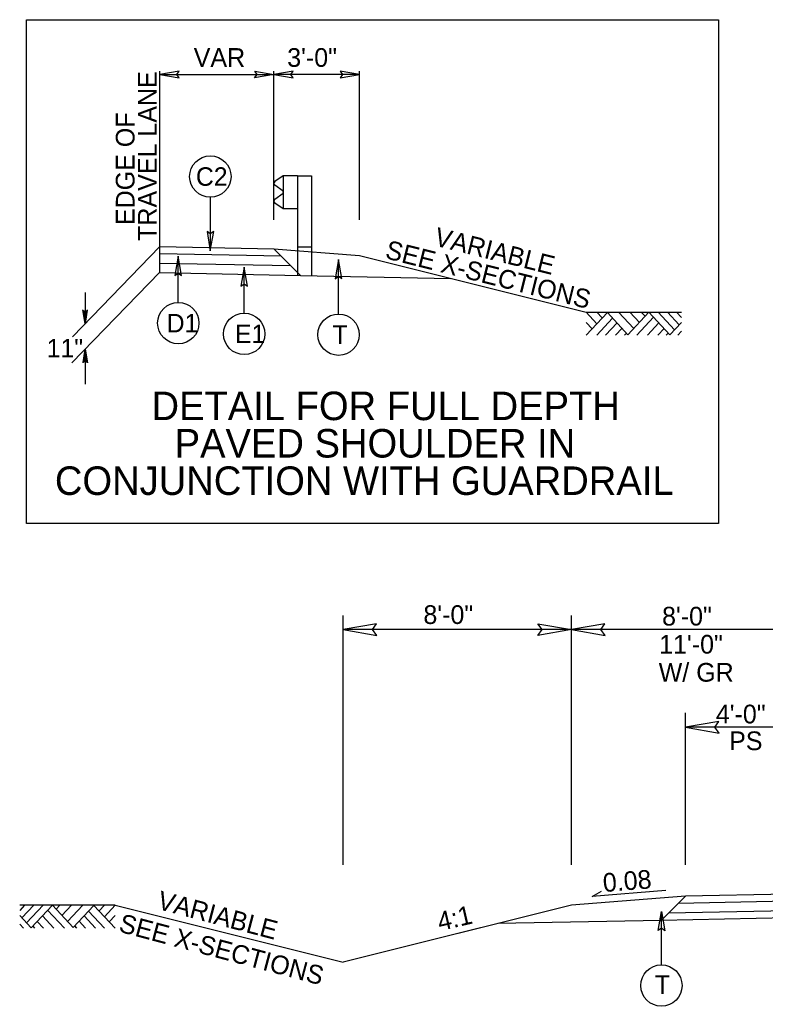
# Model space of a CAD drawing. Extents: x 1901582 to 1902252, y 193723 to 194156.
# Drawn here: x 1902035.74 to 1902061.88, y 194070.53 to 194105.11 of the extents above; entities that cross this region are included whole.
import ezdxf

# ---------------------------------------------------------------- set-up
doc = ezdxf.new("R2010")
doc.units = 0
for name, color, linetype in [('Old_Level_1', 7, 'Continuous'), ('Old_Level_11', 7, 'Continuous'), ('Old_Level_2', 7, 'Continuous'), ('Old_Level_20', 7, 'Continuous'), ('Prop Dimension Text', 7, 'Continuous'), ('Typical Guardrail CELL', 7, 'Continuous'), ('Typical Pavement Slope Information CELL', 7, 'Continuous'), ('Typical Slope Point Local CELL', 7, 'Continuous'), ('Typical Terminator CELL', 7, 'Continuous')]:
    doc.layers.add(name, color=color, linetype=linetype)

msp = doc.modelspace()

# ---------------------------------------------------------------- linework, layer by layer
at = {"layer": 'Old_Level_1'}
for p, q in [((1902040.658, 194096.249), (1902040.658, 194103.306)), ((1902040.658, 194103.19), (1902044.658, 194103.19)), ((1902044.658, 194098.102), (1902044.658, 194103.307)), ((1902044.658, 194098.102), (1902044.658, 194103.306)), ((1902047.658, 194103.19), (1902044.658, 194103.19)), ((1902047.658, 194098.102), (1902047.658, 194103.307)), ((1902040.658, 194097.166), (1902037.59, 194093.996)), ((1902040.655, 194096.916), (1902044.913, 194096.831)), ((1902040.66, 194097.166), (1902044.658, 194097.086)), ((1902044.658, 194097.086), (1902047.658, 194096.846)), ((1902044.658, 194097.086), (1902045.593, 194096.151)), ((1902040.648, 194096.583), (1902045.253, 194096.491)), ((1902047.658, 194096.846), (1902055.605, 194094.859)), ((1902040.641, 194096.25), (1902037.573, 194093.08)), ((1902040.641, 194096.25), (1902045.593, 194096.151)), ((1902045.593, 194096.151), (1902050.861, 194096.045)), ((1902038.039, 194095.548), (1902038.039, 194094.46)), ((1902038.039, 194094.46), (1902037.954, 194094.937)), ((1902038.039, 194094.46), (1902037.966, 194094.928)), ((1902037.978, 194094.919), (1902038.039, 194094.46)), ((1902038.039, 194094.46), (1902037.99, 194094.911)), ((1902038.003, 194094.902), (1902038.039, 194094.46)), ((1902038.039, 194094.46), (1902038.015, 194094.893)), ((1902038.027, 194094.884), (1902038.039, 194094.46)), ((1902038.039, 194094.46), (1902038.123, 194094.937)), ((1902038.111, 194094.928), (1902038.039, 194094.46)), ((1902038.039, 194094.46), (1902038.098, 194094.919)), ((1902038.086, 194094.911), (1902038.039, 194094.46)), ((1902038.039, 194094.46), (1902038.074, 194094.902)), ((1902038.062, 194094.893), (1902038.039, 194094.46)), ((1902038.039, 194094.46), (1902038.05, 194094.884)), ((1902038.039, 194094.875), (1902038.039, 194094.46)), ((1902038.039, 194093.561), (1902037.954, 194093.083)), ((1902037.966, 194093.093), (1902038.039, 194093.561)), ((1902038.039, 194093.561), (1902037.978, 194093.101)), ((1902037.99, 194093.111), (1902038.039, 194093.561)), ((1902038.039, 194093.561), (1902038.003, 194093.119)), ((1902038.015, 194093.127), (1902038.039, 194093.561)), ((1902038.039, 194093.561), (1902038.027, 194093.136)), ((1902038.039, 194093.561), (1902038.123, 194093.083)), ((1902038.05, 194093.136), (1902038.039, 194093.561)), ((1902038.039, 194093.561), (1902038.062, 194093.127)), ((1902038.074, 194093.119), (1902038.039, 194093.561)), ((1902038.039, 194093.561), (1902038.086, 194093.111)), ((1902038.098, 194093.101), (1902038.039, 194093.561)), ((1902038.039, 194093.561), (1902038.111, 194093.093)), ((1902038.039, 194093.561), (1902038.039, 194092.335)), ((1902047.086, 194075.483), (1902047.086, 194084.233)), ((1902055.086, 194075.483), (1902055.086, 194084.233)), ((1902055.086, 194083.733), (1902047.086, 194083.733)), ((1902063.086, 194083.733), (1902055.086, 194083.733)), ((1902059.086, 194075.483), (1902059.086, 194080.814)), ((1902063.086, 194080.314), (1902059.086, 194080.314)), ((1902088.586, 194074.983), (1902059.086, 194074.393)), ((1902088.586, 194074.733), (1902058.831, 194074.138)), ((1902055.086, 194074.073), (1902048.765, 194072.492)), ((1902059.086, 194074.393), (1902055.086, 194074.073)), ((1902058.236, 194073.542), (1902059.086, 194074.393)), ((1902088.586, 194074.149), (1902058.236, 194073.542)), ((1902088.586, 194074.399), (1902058.491, 194073.797)), ((1902058.236, 194073.542), (1902052.506, 194073.428))]:
    msp.add_line(p, q, dxfattribs=at)
for points in [[(1902055.605, 194094.859), (1902058.947, 194094.859)], [(1902039.086, 194074.073), (1902035.744, 194074.073)], [(1902039.086, 194074.073), (1902047.086, 194072.073)], [(1902055.086, 194074.073), (1902047.086, 194072.073)]]:
    msp.add_lwpolyline(points, dxfattribs=at)
at = {"layer": 'Old_Level_11'}
for p, q in [((1902042.427, 194098.89), (1902042.427, 194097.016)), ((1902041.304, 194095.201), (1902041.304, 194096.821)), ((1902046.924, 194094.796), (1902046.924, 194096.708)), ((1902043.614, 194094.825), (1902043.614, 194096.444)), ((1902055.605, 194094.859), (1902055.98, 194094.456)), ((1902055.605, 194094.054), (1902056.347, 194094.851)), ((1902055.98, 194094.859), (1902056.167, 194094.658)), ((1902056.347, 194094.851), (1902057.071, 194094.072)), ((1902056.738, 194094.859), (1902057.271, 194094.286)), ((1902057.071, 194094.072), (1902057.802, 194094.858)), ((1902057.136, 194094.859), (1902057.469, 194094.5)), ((1902057.538, 194094.859), (1902057.671, 194094.716)), ((1902057.802, 194094.858), (1902058.543, 194094.062)), ((1902058.124, 194094.859), (1902058.704, 194094.236)), ((1902058.457, 194094.859), (1902058.871, 194094.415)), ((1902058.777, 194094.859), (1902058.947, 194094.676)), ((1902055.605, 194094.497), (1902055.811, 194094.275)), ((1902055.979, 194094.054), (1902056.533, 194094.65)), ((1902056.288, 194094.054), (1902056.689, 194094.483)), ((1902057.381, 194094.054), (1902057.967, 194094.682)), ((1902057.751, 194094.054), (1902058.151, 194094.483)), ((1902058.543, 194094.062), (1902058.947, 194094.497)), ((1902056.635, 194094.054), (1902056.862, 194094.297)), ((1902056.946, 194094.054), (1902057.017, 194094.13)), ((1902058.117, 194094.054), (1902058.334, 194094.287)), ((1902058.412, 194094.054), (1902058.481, 194094.128)), ((1902058.813, 194094.054), (1902058.947, 194094.197)), ((1902035.914, 194074.073), (1902035.744, 194073.89)), ((1902036.234, 194074.073), (1902035.82, 194073.629)), ((1902036.567, 194074.073), (1902035.987, 194073.45)), ((1902036.889, 194074.072), (1902036.148, 194073.276)), ((1902037.62, 194073.286), (1902036.889, 194074.072)), ((1902037.153, 194074.073), (1902037.02, 194073.93)), ((1902037.555, 194074.073), (1902037.222, 194073.714)), ((1902037.953, 194074.073), (1902037.42, 194073.5)), ((1902038.344, 194074.065), (1902037.62, 194073.286)), ((1902039.086, 194073.268), (1902038.344, 194074.065)), ((1902038.711, 194074.073), (1902038.524, 194073.872)), ((1902039.086, 194074.073), (1902038.711, 194073.67)), ((1902037.31, 194073.268), (1902036.724, 194073.896)), ((1902038.712, 194073.268), (1902038.158, 194073.864)), ((1902058.242, 194071.98), (1902058.242, 194073.855)), ((1902036.148, 194073.276), (1902035.744, 194073.711)), ((1902035.878, 194073.268), (1902035.744, 194073.411)), ((1902036.574, 194073.268), (1902036.357, 194073.501)), ((1902036.94, 194073.268), (1902036.54, 194073.697)), ((1902038.056, 194073.268), (1902037.829, 194073.511)), ((1902038.403, 194073.268), (1902038.002, 194073.697)), ((1902039.086, 194073.711), (1902038.88, 194073.489)), ((1902036.279, 194073.268), (1902036.21, 194073.342)), ((1902037.745, 194073.268), (1902037.674, 194073.344))]:
    msp.add_line(p, q, dxfattribs=at)
for points in [[(1902035.977, 194105.112), (1902060.25, 194105.112), (1902060.25, 194087.454), (1902035.977, 194087.454)], [(1902041.333, 194103.306), (1902040.658, 194103.19), (1902041.337, 194103.07), (1902041.25, 194103.19)], [(1902043.983, 194103.307), (1902044.658, 194103.19), (1902043.979, 194103.07), (1902044.066, 194103.19)], [(1902045.333, 194103.306), (1902044.658, 194103.19), (1902045.337, 194103.07), (1902045.25, 194103.19)], [(1902046.983, 194103.074), (1902047.658, 194103.19), (1902046.979, 194103.31), (1902047.065, 194103.19)], [(1902042.312, 194097.687), (1902042.427, 194097.016), (1902042.547, 194097.691), (1902042.427, 194097.605)], [(1902041.42, 194096.149), (1902041.304, 194096.821), (1902041.185, 194096.146), (1902041.304, 194096.231)], [(1902047.039, 194096.036), (1902046.924, 194096.708), (1902046.804, 194096.032), (1902046.924, 194096.118)], [(1902043.729, 194095.773), (1902043.614, 194096.444), (1902043.494, 194095.769), (1902043.614, 194095.855)], [(1902058.127, 194073.183), (1902058.242, 194073.855), (1902058.362, 194073.179), (1902058.242, 194073.265)]]:
    msp.add_lwpolyline(points, close=True, dxfattribs=at)
for centre in [(1902042.427, 194099.615), (1902041.304, 194094.476), (1902043.614, 194094.1), (1902046.924, 194094.071), (1902058.242, 194071.255)]:
    msp.add_circle(centre, 0.725, dxfattribs=at)
at = {"layer": 'Typical Guardrail CELL'}
for p, q in [((1902044.981, 194099.641), (1902044.691, 194099.438)), ((1902044.981, 194099.108), (1902044.691, 194099.311)), ((1902045.478, 194099.641), (1902044.981, 194099.641)), ((1902044.981, 194099.641), (1902044.981, 194098.482)), ((1902045.478, 194099.641), (1902045.478, 194097.156)), ((1902045.478, 194099.641), (1902045.975, 194099.641)), ((1902045.975, 194099.641), (1902045.975, 194097.156)), ((1902044.981, 194099.015), (1902044.691, 194098.812)), ((1902044.981, 194099.061), (1902044.981, 194099.108)), ((1902044.981, 194099.061), (1902044.981, 194099.015)), ((1902044.981, 194098.482), (1902044.691, 194098.685)), ((1902045.478, 194098.482), (1902044.981, 194098.482)), ((1902045.478, 194097.156), (1902045.975, 194097.156)), ((1902045.478, 194097.156), (1902045.478, 194096.147)), ((1902045.975, 194097.156), (1902045.975, 194096.147))]:
    msp.add_line(p, q, dxfattribs=at)
for centre, start, end in [((1902044.736, 194099.375), 125.003, 235.0112), ((1902044.736, 194098.748), 125.0059, 235.0366)]:
    msp.add_arc(centre, 0.0776, start, end, dxfattribs=at)
at = {"layer": 'Typical Pavement Slope Information CELL'}
for p, q in [((1902058.396, 194074.589), (1902055.816, 194074.382)), ((1902055.816, 194074.382), (1902056.139, 194074.569))]:
    msp.add_line(p, q, dxfattribs=at)
at = {"layer": 'Typical Terminator CELL'}
for points in [[(1902048.258, 194083.935), (1902047.086, 194083.733), (1902048.265, 194083.524), (1902048.115, 194083.733)], [(1902053.915, 194083.935), (1902055.086, 194083.733), (1902053.908, 194083.524), (1902054.058, 194083.733)], [(1902056.258, 194083.935), (1902055.086, 194083.733), (1902056.265, 194083.524), (1902056.115, 194083.733)], [(1902060.258, 194080.516), (1902059.086, 194080.314), (1902060.265, 194080.106), (1902060.115, 194080.314)]]:
    msp.add_lwpolyline(points, close=True, dxfattribs=at)

# ---------------------------------------------------------------- texts
at = {"layer": 'Old_Level_1'}
for s, rotation, p in [('VAR', 360, (1902041.845, 194103.46)), ('3\'-0"', 360, (1902045.122, 194103.46)), ('TRAVEL LANE', 90, (1902040.55, 194097.359)), ('EDGE OF', 90, (1902039.77, 194097.914)), ('VARIABLE', 345.9638, (1902050.242, 194097.206)), ('SEE X-SECTIONS', 345.9638, (1902048.524, 194096.756)), ('VARIABLE', 345.2456, (1902040.529, 194073.952)), ('SEE X-SECTIONS', 345.1369, (1902039.183, 194073.152))]:
    msp.add_text(s, height=0.656, rotation=rotation, dxfattribs=at).set_placement(p)
for s, p in [('8\'-0"', (1902049.898, 194083.931)), ('8\'-0"', (1902058.266, 194083.876)), ('11\'-0"', (1902058.164, 194082.892)), ('W/ GR', (1902058.147, 194081.908)), ('4\'-0"', (1902060.151, 194080.446))]:
    msp.add_text(s, height=0.656, dxfattribs=at).set_placement(p)
at = {"layer": 'Old_Level_11'}
for s, p in [('DETAIL FOR FULL DEPTH', (1902040.365, 194091.076)), ('PAVED SHOULDER IN', (1902041.176, 194089.765)), ('CONJUNCTION WITH GUARDRAIL', (1902036.977, 194088.454))]:
    msp.add_text(s, height=1, dxfattribs=at).set_placement(p)
at = {"layer": 'Old_Level_2'}
msp.add_text('0.08', height=0.656, rotation=4.5739, dxfattribs=at).set_placement((1902056.216, 194074.531))
at = {"layer": 'Old_Level_20'}
for s, height, p in [('C2', 0.6491, (1902041.922, 194099.29)), ('T', 0.649, (1902046.71, 194093.747))]:
    msp.add_text(s, height=height, rotation=360, dxfattribs=at).set_placement(p)
for s, height, p in [('D1', 0.6491, (1902040.897, 194094.152)), ('E1', 0.6491, (1902043.294, 194093.775)), ('11"', 0.6491, (1902036.692, 194093.275)), ('T', 0.649, (1902058.015, 194070.962))]:
    msp.add_text(s, height=height, dxfattribs=at).set_placement(p)
at = {"layer": 'Prop Dimension Text'}
msp.add_text('PS', height=0.656, dxfattribs=at).set_placement((1902060.617, 194079.508))
at = {"layer": 'Typical Slope Point Local CELL'}
msp.add_text('4:1', height=0.656, rotation=13.0197, dxfattribs=at).set_placement((1902050.475, 194073.165))

doc.saveas('drawing.dxf')
